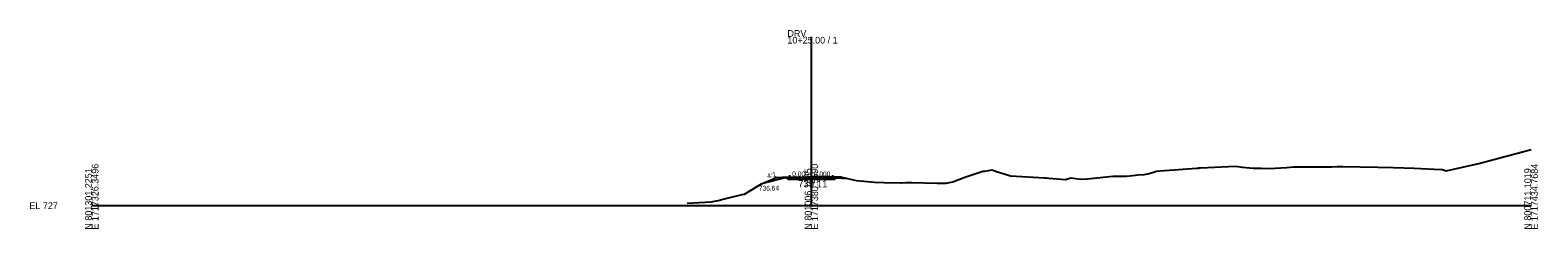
# Model space of a CAD drawing. Extents: x -26 to 603, y -10 to 3134.
# Drawn here: x -26 to 603, y 490 to 573 of the extents above; entities that cross this region are included whole.
import ezdxf

# ---------------------------------------------------------------- set-up
doc = ezdxf.new("R2010")
doc.units = 0
for name, color, linetype in [('Exist Cross Section Cell', 7, 'Continuous'), ('Exist XS Center Line Elevation Label', 7, 'Continuous'), ('Exist XS Ground Line', 7, 'Continuous'), ('Prop XS Ditch Slope Text', 7, 'Continuous'), ('Prop XS Ditch Standard Text', 7, 'Continuous'), ('Prop XS Dump Level', 7, 'Continuous'), ('Prop XS EOT Tick Mark', 7, 'Continuous'), ('Prop XS Finish Grade', 7, 'Continuous'), ('Prop XS Finish Grade Earthwork', 7, 'Continuous'), ('Prop XS Finish Grade Pavement', 7, 'Continuous'), ('Prop XS Pvmt Edge Slope', 7, 'Continuous'), ('Prop XS SE Text', 7, 'Continuous'), ('Prop XS Subgrade Earthwork', 7, 'Continuous')]:
    doc.layers.add(name, color=color, linetype=linetype)

msp = doc.modelspace()

# ---------------------------------------------------------------- linework, layer by layer
at = {"layer": 'Exist Cross Section Cell'}
for p, q in [((300, 500), (300, 570.47)), ((0, 500), (300, 500)), ((300, 500), (600, 500))]:
    msp.add_line(p, q, dxfattribs=at)
at = {"layer": 'Exist XS Ground Line'}
for p, q in [((578.25, 517.57), (600, 523.49)), ((447.16, 514.7), (460.61, 515.65)), ((460.61, 515.65), (461.27, 515.71)), ((461.27, 515.71), (461.51, 515.73)), ((461.51, 515.73), (462.17, 515.77)), ((462.17, 515.77), (476.81, 516.43)), ((476.81, 516.43), (479.68, 516.01)), ((479.68, 516.01), (484.2, 515.68)), ((484.2, 515.68), (485.94, 515.6)), ((485.94, 515.6), (487.5, 515.64)), ((487.5, 515.64), (490.79, 515.57)), ((490.79, 515.57), (498.14, 515.96)), ((498.14, 515.96), (500.99, 516.16)), ((500.99, 516.16), (511.61, 516.24)), ((511.61, 516.24), (516.87, 516.26)), ((516.87, 516.26), (519.16, 516.33)), ((519.16, 516.33), (521.4, 516.33)), ((521.4, 516.33), (536.14, 516.1)), ((536.14, 516.1), (542.7, 515.89)), ((542.7, 515.89), (551.31, 515.7)), ((551.31, 515.7), (559.59, 515.28)), ((564.68, 514.47), (578.25, 517.57)), ((279.19, 509.1), (283.51, 510.88)), ((283.51, 510.88), (285.21, 511.69)), ((285.21, 511.69), (286.03, 511.76)), ((286.03, 511.76), (287.78, 511.95)), ((287.78, 511.95), (298.72, 512.09)), ((298.72, 512.09), (300, 512.11)), ((300, 512.11), (302.54, 512.14)), ((302.54, 512.14), (306.12, 512.21)), ((306.12, 512.21), (307.73, 512.13)), ((307.73, 512.13), (312.16, 512.01)), ((312.16, 512.01), (312.43, 512)), ((312.43, 512), (312.54, 511.98)), ((312.54, 511.98), (312.74, 511.94)), ((312.74, 511.94), (318.71, 510.53)), ((318.71, 510.53), (321.79, 510.23)), ((321.79, 510.23), (326.27, 509.8)), ((326.27, 509.8), (330.24, 509.69)), ((330.24, 509.69), (337.32, 509.57)), ((337.32, 509.57), (337.73, 509.59)), ((337.73, 509.59), (339.43, 509.6)), ((339.43, 509.6), (340.89, 509.61)), ((340.89, 509.61), (341.88, 509.6)), ((341.88, 509.6), (352.44, 509.35)), ((352.44, 509.35), (356.23, 509.45)), ((356.23, 509.45), (358.98, 509.91)), ((358.98, 509.91), (363.98, 511.92)), ((363.98, 511.92), (371.42, 514.38)), ((371.42, 514.38), (372.24, 514.38)), ((372.24, 514.38), (375.39, 514.89)), ((375.39, 514.89), (377.13, 514.32)), ((377.13, 514.32), (382.59, 512.57)), ((382.59, 512.57), (382.96, 512.5)), ((382.96, 512.5), (397.19, 511.66)), ((397.19, 511.66), (397.33, 511.66)), ((397.33, 511.66), (397.47, 511.64)), ((397.47, 511.64), (397.92, 511.59)), ((397.92, 511.59), (399.01, 511.49)), ((399.01, 511.49), (405.89, 510.95)), ((405.89, 510.95), (408.12, 511.66)), ((408.12, 511.66), (412.37, 511.02)), ((412.37, 511.02), (414.76, 511.2)), ((414.76, 511.2), (416.41, 511.31)), ((416.41, 511.31), (425.66, 512.33)), ((425.66, 512.33), (431.29, 512.36)), ((431.29, 512.36), (435.12, 512.78)), ((435.12, 512.78), (436.15, 512.85)), ((436.15, 512.85), (438.72, 512.95)), ((438.72, 512.95), (440.77, 513.46)), ((440.77, 513.46), (443.84, 514.39)), ((443.84, 514.39), (445.24, 514.52)), ((445.24, 514.52), (447.16, 514.7)), ((559.59, 515.28), (562.94, 515.03)), ((562.94, 515.03), (564.68, 514.47)), ((262.17, 502.43), (264.91, 503.09)), ((264.91, 503.09), (271.2, 504.64)), ((271.2, 504.64), (272.13, 504.86)), ((272.13, 504.86), (273.97, 505.92)), ((273.97, 505.92), (279.19, 509.1)), ((248.26, 501.11), (258.21, 501.61)), ((258.21, 501.61), (261.8, 502.35)), ((261.8, 502.35), (262.17, 502.43))]:
    msp.add_line(p, q, dxfattribs=at)
at = {"layer": 'Prop XS Dump Level'}
for p, q in [((291, 511.76), (300, 511.76)), ((300, 511.76), (309, 511.76))]:
    msp.add_line(p, q, dxfattribs=at)
at = {"layer": 'Prop XS EOT Tick Mark'}
for p, q in [((291, 511.76), (291, 512.76)), ((309, 511.76), (309, 512.76))]:
    msp.add_line(p, q, dxfattribs=at)
at = {"layer": 'Prop XS Finish Grade'}
for p, q in [((291, 511.76), (289.66, 511.68)), ((309, 511.76), (310.34, 511.68))]:
    msp.add_line(p, q, dxfattribs=at)
at = {"layer": 'Prop XS Finish Grade Earthwork'}
for p, q in [((289, 511.64), (279.73, 509.32)), ((289.66, 511.68), (289, 511.64)), ((310.34, 511.68), (315.06, 511.39))]:
    msp.add_line(p, q, dxfattribs=at)
at = {"layer": 'Prop XS Finish Grade Pavement'}
for p, q in [((291, 511.76), (300, 511.76)), ((300, 511.76), (309, 511.76))]:
    msp.add_line(p, q, dxfattribs=at)
at = {"layer": 'Prop XS Pvmt Edge Slope'}
for p, q in [((291, 511.76), (290.29, 511.05)), ((309, 511.76), (309.71, 511.05))]:
    msp.add_line(p, q, dxfattribs=at)
at = {"layer": 'Prop XS Subgrade Earthwork'}
for p, q in [((290.29, 511.05), (289.66, 511.68)), ((290.29, 511.05), (300, 511.05)), ((300, 511.05), (309.71, 511.05)), ((309.71, 511.05), (310.34, 511.68))]:
    msp.add_line(p, q, dxfattribs=at)

# ---------------------------------------------------------------- texts
at = {"layer": 'Exist Cross Section Cell'}
for s, p in [('DRV', (290, 570.47)), ('10+25.00 / 1', (290, 567.67)), ('EL 727', (-26, 498.6))]:
    msp.add_text(s, height=2.8, dxfattribs=at).set_placement(p)
for s, p in [('N 801301.2251', (0, 490)), ('E 1717326.3496', (2.8, 490)), ('N 801006.1635', (300, 490)), ('E 1717380.5590', (302.8, 490)), ('N 800711.1019', (600, 490)), ('E 1717434.7684', (602.8, 490))]:
    msp.add_text(s, height=2.8, rotation=90, dxfattribs=at).set_placement(p)
at = {"layer": 'Exist XS Center Line Elevation Label'}
msp.add_text('739.11', height=3, dxfattribs=at).set_placement((294.45, 507.61))
at = {"layer": 'Prop XS Ditch Slope Text'}
msp.add_text('4:1', height=2, rotation=14.03624, dxfattribs=at).set_placement((281.77, 511.34))
at = {"layer": 'Prop XS Ditch Standard Text'}
msp.add_text('736.64', height=2, dxfattribs=at).set_placement((278.08, 506.3))
at = {"layer": 'Prop XS Dump Level'}
for p in [(289, 511.6), (311, 511.6)]:
    msp.add_text('Case1', height=0.04, dxfattribs=at).set_placement(p)
at = {"layer": 'Prop XS SE Text'}
msp.add_text('0.000', height=2, rotation=360, dxfattribs=at).set_placement((291.99, 512.26))
msp.add_text('0.000', height=2, dxfattribs=at).set_placement((300.99, 512.26))

doc.saveas('drawing.dxf')
